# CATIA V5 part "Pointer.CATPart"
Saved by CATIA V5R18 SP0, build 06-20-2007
Part number: Part1
Bounding box of the stored display mesh (mm): x -12.875 to 12.875, y -12.732 to 12.732, z 0 to 100
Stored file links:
  D:\Shriniwas\v5_r19\c16_CAT_v5r19\c16_Part\Point Curve\Pointer.CATPart
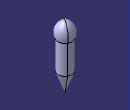
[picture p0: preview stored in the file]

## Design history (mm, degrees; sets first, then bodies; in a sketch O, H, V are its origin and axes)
Body1 (main body)
  Sketch1 on yz-plane, origin (0, 0, 0), H (0, 1, 0), V (0, 0, 1)
    line L1 (0, 0) -> (10.9446, 30.0702)
    point P1 (10.9446, 30.0702)
    line L2 (10.9446, 30.0702) -> (10.9446, 75.0702)
    point P2 (10.9446, 30.0702)
    point P3 (10.9446, 75.0702)
    arc A1 centre (-4.3336, 83.2301) radius 17.3208 from (10.9446, 75.0702) to (0, 100) ccw
    point P5 (0, 100)
    point P6 (10.9446, 91.3901)
    line L3 (0, 0) -> (0, 100)
    reference intersected line E1 through (0, 0) direction (-1, 0) from xy-plane
    reference intersected line E3 through (0, 0) direction (0, 1) from zx-plane
    radius A1 = 17.3208
    angle L1 L3 = 20
    distance O P1 = 32
    distance O P5 = 100
    distance P2 P3 = 45
    coincidence: P2 L1, P5 V, A1 P6, P6 L2, P2 P1, E3 P5, P1 L2
    vertical: L2 V, L3 V, E3 V
    horizontal: E1 H
    perpendicularity: E1 L2
  Shaft1: profile Sketch1, axis Sketch1.L3, angle 360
